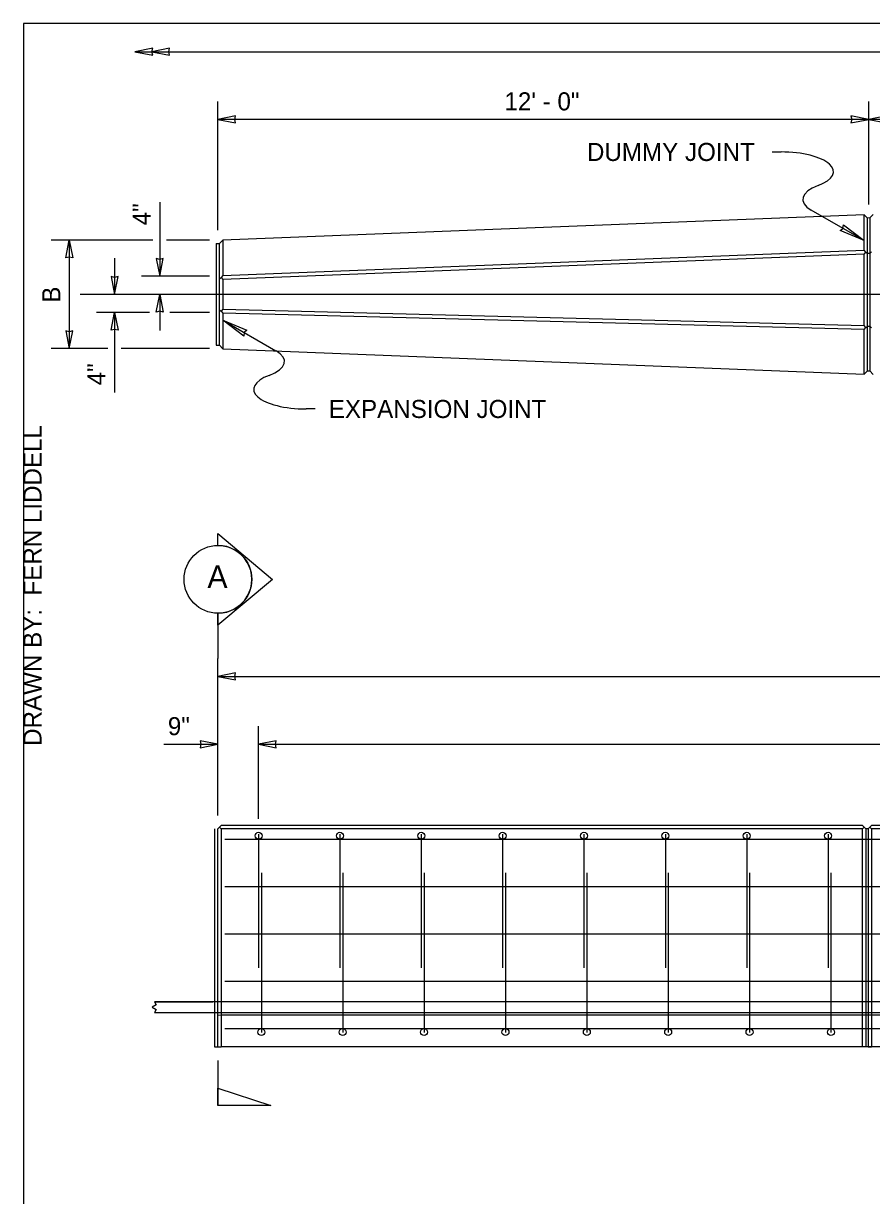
# Model space of a CAD drawing. Extents: x 99862 to 103151, y 100000 to 102076.
# Drawn here: x 99862 to 100613, y 101038 to 102076 of the extents above; entities that cross this region are included whole.
import ezdxf

# ---------------------------------------------------------------- set-up
doc = ezdxf.new("R2010")
doc.units = 0
for name, color, linetype in [('Level 1', 7, 'Continuous'), ('Level 10', 7, 'Continuous'), ('Level 14', 7, 'Continuous'), ('Level 15', 7, 'Continuous'), ('Level 2', 7, 'Continuous'), ('Level 20', 7, 'Continuous'), ('Level 3', 7, 'Continuous'), ('Level 62', 7, 'Continuous'), ('Level 8', 7, 'Continuous'), ('Level 9', 7, 'Continuous')]:
    doc.layers.add(name, color=color, linetype=linetype)

msp = doc.modelspace()

# ---------------------------------------------------------------- linework, layer by layer
at = {"layer": 'Level 1'}
msp.add_lwpolyline([(99862, 99999.5), (103151, 99999.5), (103151, 102075.5), (99862, 102075.5)], close=True, dxfattribs=at)
at = {"layer": 'Level 10'}
for p, q in [((100040.1, 101353), (101756.1, 101353)), ((100070.1, 101357.6), (100070.1, 101239.1)), ((100142.1, 101357.6), (100142.1, 101239.1)), ((100214.1, 101357.6), (100214.1, 101239.1)), ((100286.1, 101357.6), (100286.1, 101239.1)), ((100358.1, 101357.6), (100358.1, 101239.1)), ((100430.1, 101357.6), (100430.1, 101239.1)), ((100502.1, 101357.6), (100502.1, 101239.1)), ((100574.1, 101357.6), (100574.1, 101239.1)), ((100072.6, 101323.2), (100072.6, 101181.8)), ((100144.6, 101323.2), (100144.6, 101181.8)), ((100216.6, 101323.2), (100216.6, 101181.8)), ((100288.6, 101323.2), (100288.6, 101181.8)), ((100360.6, 101323.2), (100360.6, 101181.8)), ((100432.6, 101323.2), (100432.6, 101181.8)), ((100504.6, 101323.2), (100504.6, 101181.8)), ((100576.6, 101323.2), (100576.6, 101181.8)), ((100040.1, 101311.1), (101756.1, 101311.1)), ((100040.1, 101269.2), (101756.1, 101269.2)), ((100040.1, 101227.3), (101756.1, 101227.3)), ((100040.1, 101185.3), (101756.1, 101185.3))]:
    msp.add_line(p, q, dxfattribs=at)
for centre in [(100070.1, 101356.1), (100142.1, 101356.1), (100214.1, 101356.1), (100286.1, 101356.1), (100358.1, 101356.1), (100430.1, 101356.1), (100502.1, 101356.1), (100574.1, 101356.1), (100072.6, 101182.3), (100144.6, 101182.3), (100216.6, 101182.3), (100288.6, 101182.3), (100360.6, 101182.3), (100432.6, 101182.3), (100504.6, 101182.3), (100576.6, 101182.3)]:
    msp.add_circle(centre, 3.08, dxfattribs=at)
at = {"layer": 'Level 14'}
for p, q in [((100524.5, 101961.7), (100532.5, 101961.7)), ((100120.2, 101734.1), (100112.2, 101734.1))]:
    msp.add_line(p, q, dxfattribs=at)
for centre, major_axis, start_param, end_param in [((100532.5, 101944.3), (-46.4, 0), 2.356226, 4.712389), ((100598.1, 101919.7), (-46.4, 0), 5.497747, 6.859209), ((100046.6, 101776.1), (46.4, 0), 5.497747, 6.859209), ((100112.2, 101751.5), (46.4, 0), 2.356226, 4.712389)]:
    msp.add_ellipse(centre, major_axis=major_axis, ratio=0.375, start_param=start_param, end_param=end_param, dxfattribs=at)
at = {"layer": 'Level 15'}
for p, q in [((99960.6, 102050.5), (101762.1, 102050.5)), ((100034.1, 101892.5), (100034.1, 102006.5)), ((100610.1, 101915.2), (100610.1, 102006.5)), ((100610.1, 101990.5), (100034.1, 101990.5)), ((101186.1, 101990.5), (100610.1, 101990.5)), ((99982.6, 101917.1), (99982.6, 101851.6)), ((100606.1, 101883.2), (100559.2, 101910.2)), ((99976.6, 101883.6), (99886.6, 101883.6)), ((99902.6, 101883.6), (99902.6, 101787.6)), ((100026.6, 101883.6), (99988.6, 101883.6)), ((99942.6, 101867.6), (99942.6, 101835.6)), ((100026.6, 101851.6), (99966.6, 101851.6)), ((101842.9, 101835.5), (99912.2, 101835.5)), ((99982.6, 101835.6), (99982.6, 101803.6)), ((99973.6, 101819.6), (99926.6, 101819.6)), ((99942.6, 101819.6), (99942.6, 101748.7)), ((100026.6, 101819.6), (99991.6, 101819.6)), ((100038.6, 101812.7), (100085.5, 101785.6)), ((99936.6, 101787.6), (99886.6, 101787.6)), ((100026.6, 101787.6), (99948.6, 101787.6)), ((100034.1, 101374.2), (100034.1, 101513.2)), ((100034.1, 101497.2), (101762.1, 101497.2)), ((100070.1, 101371.2), (100070.1, 101453.2)), ((99986.1, 101437.2), (100034.1, 101437.2)), ((100070.1, 101437.2), (101726.1, 101437.2))]:
    msp.add_line(p, q, dxfattribs=at)
for points in [[(99960.6, 102050.5), (99976.4, 102047.4), (99975.6, 102050.5), (99976.4, 102053.6)], [(99975.6, 102050.5), (99991.4, 102047.4), (99990.6, 102050.5), (99991.4, 102053.6)], [(100034.1, 101990.5), (100049.8, 101987.4), (100049.1, 101990.5), (100049.8, 101993.6)], [(100610.1, 101990.5), (100594.4, 101993.6), (100595.1, 101990.5), (100594.4, 101987.4)], [(100610.1, 101990.5), (100625.8, 101987.4), (100625.1, 101990.5), (100625.8, 101993.6)], [(100606.1, 101883.2), (100584.8, 101892), (100587.2, 101894), (100587.8, 101897.2)], [(99902.6, 101883.6), (99905.7, 101867.8), (99902.6, 101868.6), (99899.5, 101867.8)], [(99982.6, 101851.6), (99985.7, 101867.3), (99982.6, 101866.5), (99979.5, 101867.3)], [(99942.6, 101835.6), (99945.7, 101851.3), (99942.6, 101850.5), (99939.5, 101851.3)], [(99982.6, 101835.6), (99985.7, 101819.8), (99982.6, 101820.6), (99979.5, 101819.8)], [(99942.6, 101819.6), (99945.7, 101803.8), (99942.6, 101804.6), (99939.5, 101803.8)], [(100038.6, 101812.7), (100059.8, 101803.8), (100057.4, 101801.8), (100056.9, 101798.7)], [(99902.6, 101787.6), (99905.7, 101803.3), (99902.6, 101802.5), (99899.5, 101803.3)], [(100034.1, 101497.2), (100049.8, 101494.1), (100049.1, 101497.2), (100049.8, 101500.3)], [(100034.1, 101437.2), (100018.4, 101440.3), (100019.1, 101437.2), (100018.4, 101434.1)], [(100070.1, 101437.2), (100085.8, 101434.1), (100085.1, 101437.2), (100085.8, 101440.3)]]:
    msp.add_lwpolyline(points, close=True, dxfattribs=at)
at = {"layer": 'Level 2'}
for p, q in [((100606.1, 101906.1), (100038.6, 101883.6)), ((100609.1, 101903.2), (100606.1, 101906.1)), ((100611.1, 101903.3), (100609.1, 101903.2)), ((100614.1, 101906.3), (100611.1, 101903.3)), ((100032.6, 101880.5), (100035.6, 101880.6)), ((100032.6, 101880.5), (100032.6, 101790.5)), ((100038.6, 101883.6), (100035.6, 101880.6)), ((100035.6, 101849.1), (100035.6, 101880.6)), ((100038.6, 101883.6), (100038.6, 101852.2)), ((100038.6, 101852.2), (100606.1, 101874.7)), ((100606.1, 101871.1), (100038.6, 101848.6)), ((100037.1, 101850.4), (100035.6, 101849.1)), ((100035.6, 101822), (100035.6, 101849.1)), ((100038.6, 101852.2), (100037.1, 101850.4)), ((100037.1, 101850.4), (100038.6, 101848.6)), ((100038.6, 101848.6), (100038.6, 101822.4)), ((100035.6, 101790.5), (100035.6, 101822)), ((100035.6, 101822), (100037.1, 101820.7)), ((100038.6, 101822.4), (100037.1, 101820.7)), ((100037.1, 101820.7), (100038.6, 101818.9)), ((100038.6, 101822.4), (100606.1, 101808)), ((100606.1, 101804.4), (100038.6, 101818.9)), ((100038.6, 101818.9), (100038.6, 101787.4)), ((100032.6, 101790.5), (100035.6, 101790.5)), ((100035.6, 101790.5), (100038.6, 101787.4)), ((100038.6, 101787.4), (100606.1, 101764.9)), ((100606.1, 101764.9), (100609.1, 101767.9)), ((100609.1, 101767.9), (100611.1, 101767.8)), ((100611.1, 101767.8), (100614.1, 101764.7)), ((100031.1, 101362.2), (100031.1, 101169.2)), ((100035.6, 101363.7), (100034.1, 101362.2)), ((100034.1, 101196.9), (100034.1, 101362.2)), ((100035.6, 101363.7), (100037.1, 101365.2)), ((100037.1, 101362.2), (100035.6, 101363.7)), ((100604.6, 101365.2), (100037.1, 101365.2)), ((100604.6, 101362.2), (100037.1, 101362.2)), ((100037.1, 101362.2), (100037.1, 101197.2)), ((100606.1, 101363.7), (100604.6, 101365.2)), ((100604.6, 101362.2), (100606.1, 101363.7)), ((100604.6, 101169.2), (100604.6, 101362.2)), ((100606.1, 101363.7), (100607.6, 101362.2)), ((100609.6, 101362.2), (100607.6, 101362.2)), ((100607.6, 101362.2), (100607.6, 101169.2)), ((100611.1, 101363.7), (100609.6, 101362.2)), ((100609.6, 101362.2), (100609.6, 101169.2)), ((100611.1, 101363.7), (100612.6, 101365.2)), ((100612.6, 101362.2), (100611.1, 101363.7)), ((101180.1, 101365.2), (100612.6, 101365.2)), ((100612.6, 101362.2), (100612.6, 101169.2)), ((101180.1, 101362.2), (100612.6, 101362.2)), ((100037.1, 101197.2), (100034.1, 101196.9)), ((100034.1, 101169.2), (100034.1, 101196.9)), ((101759.1, 101197.2), (100037.1, 101197.2)), ((100037.1, 101197.2), (100037.1, 101169.2)), ((100031.1, 101169.2), (100037.1, 101169.2)), ((101759.1, 101169.2), (100037.1, 101169.2)), ((100607.6, 101169.2), (100604.6, 101169.2)), ((100609.6, 101169.2), (100607.6, 101169.2)), ((100609.6, 101169.2), (100612.6, 101169.2))]:
    msp.add_line(p, q, dxfattribs=at)
at = {"layer": 'Level 3'}
for p, q in [((100606.1, 101874.7), (100606.1, 101906.1)), ((100609.1, 101871.7), (100609.1, 101903.2)), ((100611.1, 101903.3), (100611.1, 101871.8)), ((100607.6, 101872.9), (100606.1, 101874.7)), ((100606.1, 101871.1), (100607.6, 101872.9)), ((100606.1, 101808), (100606.1, 101871.1)), ((100607.6, 101872.9), (100609.1, 101871.7)), ((100611.1, 101871.8), (100609.1, 101871.7)), ((100609.1, 101807.4), (100609.1, 101871.7)), ((100611.1, 101871.8), (100612.6, 101873.1)), ((100611.1, 101871.8), (100611.1, 101807.3)), ((100607.6, 101806.1), (100606.1, 101808)), ((100607.6, 101806.1), (100609.1, 101807.4)), ((100609.1, 101767.9), (100609.1, 101807.4)), ((100609.1, 101807.4), (100611.1, 101807.3)), ((100611.1, 101807.3), (100611.1, 101767.8)), ((100611.1, 101807.3), (100612.6, 101806)), ((100606.1, 101804.4), (100607.6, 101806.1)), ((100606.1, 101764.9), (100606.1, 101804.4))]:
    msp.add_line(p, q, dxfattribs=at)
at = {"layer": 'Level 8'}
msp.add_line((99977.9, 101209.2), (100029.5, 101209.2), dxfattribs=at)
msp.add_lwpolyline([(101136.5, 101209.2), (99977.9, 101209.2), (99979.4, 101206.3), (99976, 101204.3), (99979.6, 101202.3), (99977.9, 101199.6), (101138.8, 101199.6)], dxfattribs=at)
at = {"layer": 'Level 9'}
for p, q in [((100034.1, 101613.2), (100034.1, 101623.8)), ((100034.1, 101623.8), (100082.5, 101583.2)), ((100082.5, 101583.2), (100034.1, 101542.6)), ((100034.1, 101542.6), (100034.1, 101553.2)), ((100034.1, 101553.2), (100034.1, 101513.2)), ((100034.1, 101157.2), (100034.1, 101117.2))]:
    msp.add_line(p, q, dxfattribs=at)
msp.add_lwpolyline([(100034.1, 101132.7), (100081, 101117.2), (100034.1, 101117.2)], close=True, dxfattribs=at)
msp.add_circle((100034.1, 101583.2), 30, dxfattribs=at)
msp.add_arc((100034.1, 101583.2), 30, 269.9978, 90.0022, dxfattribs=at)

# ---------------------------------------------------------------- texts
at = {"layer": 'Level 20'}
for s, height, p in [('12\' - 0"', 16, (100287.7, 101998.5)), ('DUMMY JOINT', 16, (100360.7, 101953.7)), ('EXPANSION JOINT', 16, (100132.2, 101726.1)), ('A', 20, (100024.8, 101575.6)), ('9"', 16, (99989.8, 101445.2))]:
    msp.add_text(s, height=height, dxfattribs=at).set_placement(p)
for s, p in [('4"', (99974.6, 101896.7)), ('B', (99894.6, 101828.2)), ('4"', (99934.6, 101755))]:
    msp.add_text(s, height=16, rotation=90, dxfattribs=at).set_placement(p)
at = {"layer": 'Level 62'}
msp.add_text('DRAWN BY:  FERN LIDDELL', height=16, rotation=90, dxfattribs=at).set_placement((99878, 101435.7))

doc.saveas('drawing.dxf')
